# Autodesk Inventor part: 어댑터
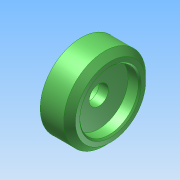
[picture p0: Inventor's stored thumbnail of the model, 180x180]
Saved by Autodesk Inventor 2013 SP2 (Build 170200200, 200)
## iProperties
Created: 2025-09
Part Number: 어댑터
Material: Generic
Document SubType Name: Modeling
Designer: a
Density: 1 g/cm^3
Author: a
변환 표준: STEP AP214IS
전처리기: Build: 200, Release: 2013 SP2 Update 6 - Date: Thu 07/17/2014
전송 단위: 밀리미터
불확실성: 0.01
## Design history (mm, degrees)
node "어댑터1"
node "솔리드1"
node "기준1"
